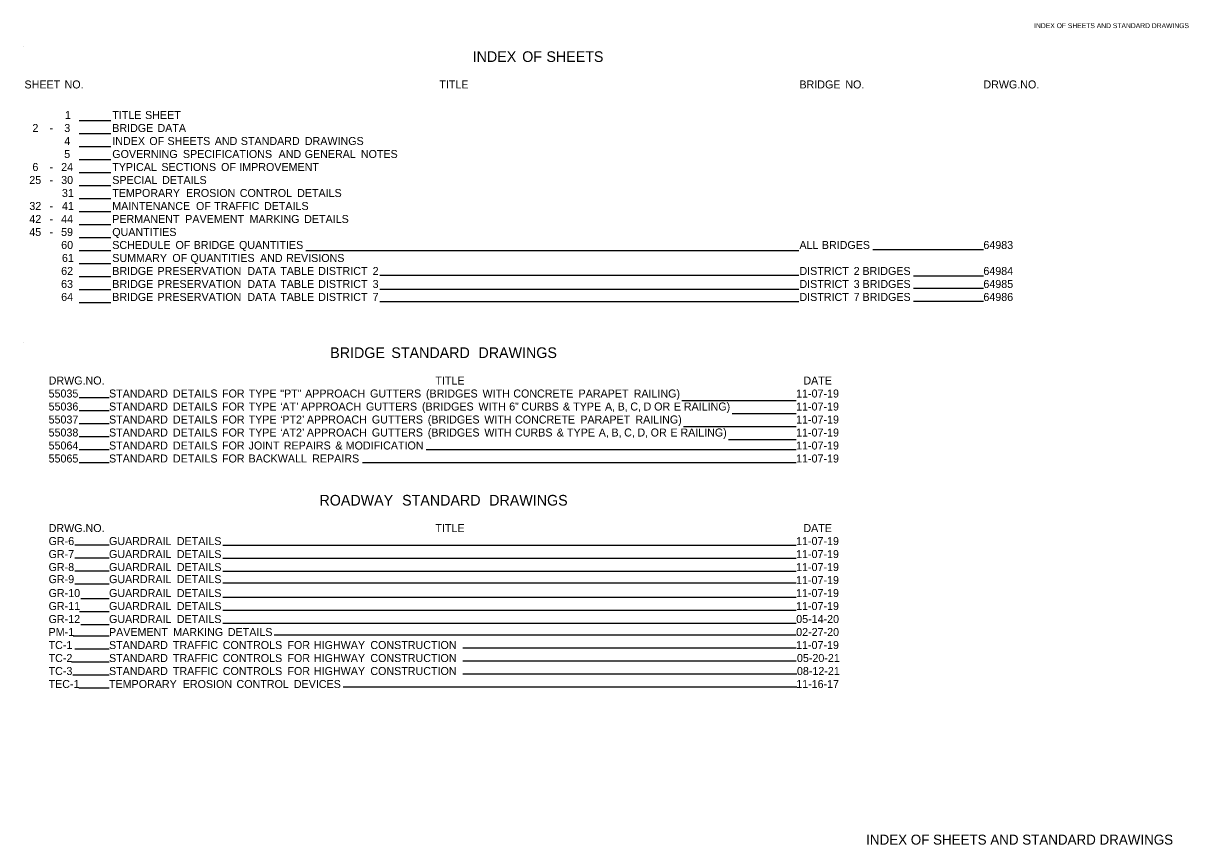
# Model space of a CAD drawing. Extents: x 1930556 to 1931949, y 596452 to 599546.
import ezdxf

# ---------------------------------------------------------------- set-up
doc = ezdxf.new("R2010")
doc.units = 0
for name, color, linetype in [('Default', 7, 'Continuous'), ('R_Border', 7, 'Continuous'), ('R_Border Prem', 7, 'Continuous')]:
    doc.layers.add(name, color=color, linetype=linetype)

msp = doc.modelspace()

# ---------------------------------------------------------------- linework, layer by layer
at = {"layer": 'Default'}
for p, q in [((1930556.1, 599518), (1930556.1, 599518)), ((1930623.2, 599429.1), (1930661.4, 599429.1)), ((1930623.2, 599413.5), (1930661.4, 599413.5)), ((1930623.2, 599397.9), (1930661.4, 599397.9)), ((1930623.2, 599382.3), (1930661.4, 599382.3)), ((1930623.2, 599366.7), (1930661.4, 599366.7)), ((1930623.2, 599351.1), (1930661.4, 599351.1)), ((1930623.2, 599335.5), (1930661.4, 599335.5)), ((1930623.2, 599319.9), (1930661.4, 599319.9)), ((1930623.2, 599304.3), (1930661.4, 599304.3)), ((1930623.2, 599288.7), (1930661.4, 599288.7)), ((1930623.2, 599273.1), (1930661.4, 599273.1)), ((1930895.4, 599273.3), (1931486.8, 599273.3)), ((1931575.7, 599274.2), (1931708.2, 599274.2)), ((1930623.2, 599257.5), (1930661.4, 599257.5)), ((1930623.2, 599241.9), (1930661.4, 599241.9)), ((1930983.9, 599243.4), (1931486.8, 599243.4)), ((1931624.2, 599242.6), (1931708.2, 599242.6)), ((1930623.2, 599226.3), (1930661.4, 599226.3)), ((1930983.9, 599226.7), (1931486.8, 599226.7)), ((1931624.2, 599227.8), (1931708.2, 599227.8)), ((1930623.2, 599210.7), (1930661.4, 599210.7)), ((1930983.9, 599211.9), (1931486.8, 599211.9)), ((1931624.2, 599212.4), (1931708.2, 599212.4)), ((1930556.1, 599162.6), (1930556.1, 599162.6)), ((1930623.3, 599096.7), (1930659.1, 599096.7)), ((1931346.3, 599093), (1931483.5, 599093)), ((1930623.2, 599081.1), (1930659.1, 599081.1)), ((1931406.6, 599077.4), (1931483.5, 599077.4)), ((1930623.2, 599065.5), (1930659.1, 599065.5)), ((1931348.5, 599061.8), (1931483.5, 599061.8)), ((1930623.3, 599049.9), (1930659.1, 599049.9)), ((1931402.4, 599046.2), (1931483.5, 599046.2)), ((1930623.3, 599034.3), (1930659.1, 599034.3)), ((1931039.7, 599034.2), (1931483.5, 599034.2)), ((1930623.3, 599018.7), (1930659.1, 599018.7)), ((1930963.4, 599018.6), (1931483.5, 599018.6)), ((1930618.1, 598919.8), (1930659.1, 598919.8)), ((1930795.8, 598919.5), (1931483.5, 598919.5)), ((1930618, 598904.2), (1930659.1, 598904.2)), ((1930795.8, 598903.9), (1931483.5, 598903.9)), ((1930618, 598888.6), (1930659.1, 598888.6)), ((1930795.8, 598888.3), (1931483.5, 598888.3)), ((1930618, 598873), (1930659.1, 598873)), ((1930795.8, 598874.2), (1931483.5, 598874.2)), ((1930625.4, 598855.3), (1930659.1, 598855.3)), ((1930795.8, 598857.1), (1931483.5, 598857.1)), ((1930623.6, 598839.7), (1930659.1, 598839.7)), ((1930795.8, 598841.5), (1931483.5, 598841.5)), ((1930625.4, 598824.1), (1930659.1, 598824.1)), ((1930795.8, 598825.9), (1931483.6, 598825.9)), ((1930616.1, 598810.5), (1930659.1, 598810.5)), ((1930857.1, 598811.8), (1931483.6, 598811.8)), ((1930617.9, 598794.9), (1930659.1, 598794.9)), ((1931083.6, 598796.2), (1931483.6, 598796.2)), ((1930613.9, 598779.3), (1930659.1, 598779.3)), ((1931083.6, 598780.6), (1931483.5, 598780.6)), ((1930615.7, 598763.7), (1930659.1, 598763.7)), ((1931083.6, 598765), (1931484.5, 598765)), ((1930622.8, 598748.2), (1930659.1, 598748.2)), ((1930940.1, 598749.4), (1931484.5, 598749.4))]:
    msp.add_line(p, q, dxfattribs=at)

# ---------------------------------------------------------------- texts
for s, height, p in [('INDEX', 12.8, (1931095.4, 599499.5)), (' OF', 12.8, (1931150.1, 599499.5)), (' SHEETS', 12.8, (1931179.1, 599499.5)), ('SHEET', 9.6, (1930557.7, 599467.7)), (' NO.', 9.6, (1930602.2, 599467.7)), ('TITLE', 9.6, (1931055.4, 599467.7)), ('BRIDGE', 9.6, (1931487.5, 599467.7)), (' NO.', 9.6, (1931539, 599467.7)), ('DRWG.NO.', 9.6, (1931708.2, 599467.7)), ('1', 9.6, (1930606.3, 599431)), ('TITLE', 9.6, (1930663, 599431)), (' SHEET', 9.6, (1930698.8, 599431)), ('2', 9.6, (1930567.2, 599415.4)), ('-', 9.6, (1930587.7, 599415.4)), ('3', 9.6, (1930605.4, 599415.4)), ('BRIDGE', 9.6, (1930663, 599415.4)), (' DATA', 9.6, (1930713.7, 599415.4)), ('4', 9.6, (1930605.4, 599399.8)), ('INDEX', 9.6, (1930663, 599399.8)), (' OF', 9.6, (1930703.9, 599399.8)), (' SHEETS', 9.6, (1930725.7, 599399.8)), (' AND', 9.6, (1930782.4, 599399.8)), (' STANDARD', 9.6, (1930813.7, 599399.8)), (' DRAWINGS', 9.6, (1930890.5, 599399.8)), ('5', 9.6, (1930605.3, 599384.2)), ('GOVERNING', 9.6, (1930663, 599384.2)), (' SPECIFICATIONS', 9.6, (1930744.2, 599384.2)), (' AND', 9.6, (1930859, 599384.2)), (' GENERAL', 9.6, (1930890.3, 599384.2)), (' NOTES', 9.6, (1930957.7, 599384.2)), ('6', 9.6, (1930567.2, 599368.6)), ('24', 9.6, (1930601.7, 599368.6)), ('TYPICAL', 9.6, (1930663, 599368.6)), (' SECTIONS', 9.6, (1930718.4, 599368.6)), (' OF', 9.6, (1930790, 599368.6)), (' IMPROVEMENT', 9.6, (1930811.8, 599368.6)), ('25', 9.6, (1930563.4, 599353)), ('-', 9.6, (1930587.7, 599368.6)), ('30', 9.6, (1930601.7, 599353)), ('SPECIAL', 9.6, (1930663, 599353)), (' DETAILS', 9.6, (1930719.2, 599353)), ('-', 9.6, (1930587.7, 599353)), ('31', 9.6, (1930602.6, 599337.4)), ('TEMPORARY', 9.6, (1930663, 599337.4)), (' EROSION', 9.6, (1930747.9, 599337.4)), (' CONTROL', 9.6, (1930812.4, 599337.4)), (' DETAILS', 9.6, (1930881.2, 599337.4)), ('32', 9.6, (1930563.5, 599321.8)), ('-', 9.6, (1930587.7, 599321.8)), ('41', 9.6, (1930602.6, 599321.8)), ('MAINTENANCE', 9.6, (1930663, 599321.8)), (' OF', 9.6, (1930759.9, 599321.8)), (' TRAFFIC', 9.6, (1930781.7, 599321.8)), (' DETAILS', 9.6, (1930841.5, 599321.8)), ('42', 9.6, (1930563.5, 599306.2)), ('-', 9.6, (1930587.7, 599306.2)), ('44', 9.6, (1930601.7, 599306.2)), ('PERMANENT', 9.6, (1930663, 599306.2)), (' PAVEMENT', 9.6, (1930747, 599306.2)), (' MARKING', 9.6, (1930824.2, 599306.2)), (' DETAILS', 9.6, (1930889.7, 599306.2)), ('45', 9.6, (1930563.4, 599290.6)), ('-', 9.6, (1930587.7, 599290.6)), ('59', 9.6, (1930601.6, 599290.6)), ('QUANTITIES', 9.6, (1930663, 599290.6)), ('60', 9.6, (1930601.7, 599275)), ('SCHEDULE', 9.6, (1930663, 599275)), (' OF', 9.6, (1930735.3, 599275)), (' BRIDGE', 9.6, (1930757.1, 599275)), (' QUANTITIES', 9.6, (1930811.5, 599275)), ('ALL', 9.6, (1931487.5, 599275)), (' BRIDGES', 9.6, (1931510.8, 599275)), ('64983', 9.6, (1931708.2, 599275)), ('61', 9.6, (1930602.6, 599259.4)), ('SUMMARY', 9.6, (1930663, 599259.4)), (' OF', 9.6, (1930731.5, 599259.4)), (' QUANTITIES', 9.6, (1930753.2, 599259.4)), (' AND', 9.6, (1930836.7, 599259.4)), (' REVISIONS', 9.6, (1930868.1, 599259.4)), ('62', 9.6, (1930601.7, 599243.8)), ('BRIDGE', 9.6, (1930663, 599243.8)), (' PRESERVATION', 9.6, (1930713.7, 599243.8)), (' DATA', 9.6, (1930821.5, 599243.8)), (' TABLE', 9.6, (1930861, 599243.8)), (' DISTRICT', 9.6, (1930906.5, 599243.8)), (' 2', 9.6, (1930971.8, 599243.8)), ('DISTRICT', 9.6, (1931487.5, 599243.8)), (' 2', 9.6, (1931549, 599243.8)), (' BRIDGES', 9.6, (1931559.5, 599243.8)), ('64984', 9.6, (1931708.2, 599243.8)), ('63', 9.6, (1930601.6, 599228.2)), ('BRIDGE', 9.6, (1930663, 599228.2)), (' PRESERVATION', 9.6, (1930713.7, 599228.2)), (' DATA', 9.6, (1930821.5, 599228.2)), (' TABLE', 9.6, (1930861, 599228.2)), (' DISTRICT', 9.6, (1930906.5, 599228.2)), (' 3', 9.6, (1930971.8, 599228.2)), ('DISTRICT', 9.6, (1931487.5, 599228.2)), (' 3', 9.6, (1931549, 599228.2)), (' BRIDGES', 9.6, (1931559.6, 599228.2)), ('64985', 9.6, (1931708.2, 599228.2)), ('64', 9.6, (1930601.7, 599212.6)), ('BRIDGE', 9.6, (1930663, 599212.6)), (' PRESERVATION', 9.6, (1930713.7, 599212.6)), (' DATA', 9.6, (1930821.5, 599212.6)), (' TABLE', 9.6, (1930861, 599212.6)), (' DISTRICT', 9.6, (1930906.5, 599212.6)), (' 7', 9.6, (1930971.8, 599212.6)), ('DISTRICT', 9.6, (1931487.5, 599212.6)), (' 7', 9.6, (1931549, 599212.6)), (' BRIDGES', 9.6, (1931559.6, 599212.6)), ('64986', 9.6, (1931708.2, 599212.6)), ('BRIDGE', 12.8, (1930924.5, 599144.1)), (' STANDARD', 12.8, (1930993.1, 599144.1)), (' DRAWINGS', 12.8, (1931097.6, 599144.1)), ('DRWG.NO.', 9.6, (1930586.7, 599112.3)), ('TITLE', 9.6, (1931050.7, 599112.3)), ('DATE', 9.6, (1931492.2, 599112.3)), ('55035', 9.6, (1930586.6, 599096.7)), ('STANDARD', 9.6, (1930659.1, 599096.7)), (' DETAILS', 9.6, (1930732.2, 599096.7)), (' FOR', 9.6, (1930791.1, 599096.7)), (' TYPE', 9.6, (1930823, 599096.7)), (' "PT"', 9.6, (1930861, 599096.7)), (' APPROACH', 9.6, (1930890.8, 599096.7)), (' GUTTERS', 9.6, (1930968.7, 599096.7)), (' (BRIDGES', 9.6, (1931035.8, 599096.7)), (' WITH', 9.6, (1931103.7, 599096.7)), (' CONCRETE', 9.6, (1931140.6, 599096.7)), (' PARAPET', 9.6, (1931218.9, 599096.7)), (' RAILING)', 9.6, (1931285, 599096.7)), ('11-07-19', 9.6, (1931483.5, 599096.7)), ('55036', 9.6, (1930586.6, 599081.1)), ('STANDARD', 9.6, (1930659.1, 599081.1)), (' DETAILS', 9.6, (1930732.2, 599081.1)), (' FOR', 9.6, (1930791.1, 599081.1)), (' TYPE', 9.6, (1930823, 599081.1)), ('‘', 9.6, (1930864.7, 599081.1)), ('AT', 9.6, (1930867, 599081.1)), ('’', 9.6, (1930883.8, 599081.1)), (' APPROACH', 9.6, (1930885.9, 599081.1)), (' GUTTERS', 9.6, (1930963.8, 599081.1)), (' (BRIDGES', 9.6, (1931031, 599081.1)), (' WITH', 9.6, (1931098.8, 599081.1)), (' 6', 9.6, (1931135.7, 599081.1)), ('”', 9.6, (1931146.3, 599081.1)), (' CURBS', 9.6, (1931150.2, 599081.1)), (' &', 9.6, (1931200.2, 599081.1)), (' TYPE', 9.6, (1931212.5, 599081.1)), (' A,', 9.6, (1931250.6, 599081.1)), (' B,', 9.6, (1931265.8, 599081.1)), (' C,', 9.6, (1931281, 599081.1)), (' D', 9.6, (1931296.9, 599081.1)), (' OR', 9.6, (1931309.6, 599081.1)), (' E', 9.6, (1931333.3, 599081.1)), (' RAILING)', 9.6, (1931345.2, 599081.1)), ('11-07-19', 9.6, (1931483.5, 599081.1)), ('55037', 9.6, (1930586.6, 599065.5)), ('STANDARD', 9.6, (1930659.1, 599065.5)), (' DETAILS', 9.6, (1930732.2, 599065.5)), (' FOR', 9.6, (1930791.1, 599065.5)), (' TYPE', 9.6, (1930823, 599065.5)), ('‘', 9.6, (1930864.7, 599065.5)), ('PT2', 9.6, (1930867, 599065.5)), ('’', 9.6, (1930890.8, 599065.5)), (' APPROACH', 9.6, (1930892.9, 599065.5)), (' GUTTERS', 9.6, (1930970.9, 599065.5)), (' (BRIDGES', 9.6, (1931038, 599065.5)), (' WITH', 9.6, (1931105.8, 599065.5)), (' CONCRETE', 9.6, (1931142.7, 599065.5)), (' PARAPET', 9.6, (1931221, 599065.5)), (' RAILING)', 9.6, (1931287.1, 599065.5)), ('11-07-19', 9.6, (1931483.5, 599065.5)), ('55038', 9.6, (1930586.6, 599049.9)), ('STANDARD', 9.6, (1930659.1, 599049.9)), (' DETAILS', 9.6, (1930732.2, 599049.9)), (' FOR', 9.6, (1930791.1, 599049.9)), (' TYPE', 9.6, (1930823, 599049.9)), ('‘', 9.6, (1930864.7, 599049.9)), ('AT2', 9.6, (1930867, 599049.9)), ('’', 9.6, (1930890.8, 599049.9)), (' APPROACH', 9.6, (1930892.9, 599049.9)), (' GUTTERS', 9.6, (1930970.9, 599049.9)), (' (BRIDGES', 9.6, (1931038, 599049.9)), (' WITH', 9.6, (1931105.8, 599049.9)), (' CURBS', 9.6, (1931142.7, 599049.9)), (' &', 9.6, (1931192.7, 599049.9)), (' TYPE', 9.6, (1931205.1, 599049.9)), (' A,', 9.6, (1931243.1, 599049.9)), (' B,', 9.6, (1931258.4, 599049.9)), (' C,', 9.6, (1931273.6, 599049.9)), (' D,', 9.6, (1931289.5, 599049.9)), (' OR', 9.6, (1931305.4, 599049.9)), (' E', 9.6, (1931329.1, 599049.9)), (' RAILING)', 9.6, (1931341.1, 599049.9)), ('11-07-19', 9.6, (1931483.5, 599049.9)), ('55064', 9.6, (1930586.6, 599034.3)), ('STANDARD', 9.6, (1930659.1, 599034.3)), (' DETAILS', 9.6, (1930732.2, 599034.3)), (' FOR', 9.6, (1930791.1, 599034.3)), (' JOINT', 9.6, (1930823, 599034.3)), (' REPAIRS', 9.6, (1930865.2, 599034.3)), (' &', 9.6, (1930927.1, 599034.3)), (' MODIFICATION', 9.6, (1930939.5, 599034.3)), ('11-07-19', 9.6, (1931483.5, 599034.3)), ('55065', 9.6, (1930586.6, 599018.7)), ('STANDARD', 9.6, (1930659.1, 599018.7)), (' DETAILS', 9.6, (1930732.2, 599018.7)), (' FOR', 9.6, (1930791.1, 599018.7)), (' BACKWALL', 9.6, (1930823, 599018.7)), (' REPAIRS', 9.6, (1930899.3, 599018.7)), ('11-07-19', 9.6, (1931483.5, 599018.7)), ('ROADWAY', 12.8, (1930911.6, 598967)), (' STANDARD', 12.8, (1931006, 598967)), (' DRAWINGS', 12.8, (1931110.5, 598967)), ('DRWG.NO.', 9.6, (1930586.7, 598935.2)), ('TITLE', 9.6, (1931050.7, 598935.2)), ('DATE', 9.6, (1931492.2, 598935.2)), ('GR-6', 9.6, (1930586.6, 598919.6)), ('GUARDRAIL', 9.6, (1930659.1, 598919.6)), (' DETAILS', 9.6, (1930736.9, 598919.6)), ('11-07-19', 9.6, (1931483.5, 598919.6)), ('GR-7', 9.6, (1930586.6, 598904)), ('GUARDRAIL', 9.6, (1930659.1, 598904)), (' DETAILS', 9.6, (1930736.9, 598904)), ('11-07-19', 9.6, (1931483.5, 598904)), ('GR-8', 9.6, (1930586.6, 598888.4)), ('GUARDRAIL', 9.6, (1930659.1, 598888.4)), (' DETAILS', 9.6, (1930736.9, 598888.4)), ('11-07-19', 9.6, (1931483.5, 598888.4)), ('GR-9', 9.6, (1930586.6, 598873.9)), ('GUARDRAIL', 9.6, (1930659.1, 598873.9)), (' DETAILS', 9.6, (1930736.9, 598873.9)), ('11-07-19', 9.6, (1931483.5, 598872.8)), ('GR-10', 9.6, (1930586.6, 598857.2)), ('GUARDRAIL', 9.6, (1930659.1, 598857.2)), (' DETAILS', 9.6, (1930736.9, 598857.2)), ('11-07-19', 9.6, (1931483.5, 598857.2)), ('GR-11', 9.6, (1930586.6, 598841.6)), ('GUARDRAIL', 9.6, (1930659.1, 598841.6)), (' DETAILS', 9.6, (1930736.9, 598841.6)), ('11-07-19', 9.6, (1931483.5, 598841.6)), ('GR-12', 9.6, (1930586.6, 598826)), ('GUARDRAIL', 9.6, (1930659.1, 598826)), (' DETAILS', 9.6, (1930736.9, 598826)), ('05-14-20', 9.6, (1931483.6, 598826)), ('PM-1', 9.6, (1930586.6, 598810.4)), ('PAVEMENT', 9.6, (1930659.1, 598810.4)), (' MARKING', 9.6, (1930732.6, 598810.4)), (' DETAILS', 9.6, (1930798.1, 598810.4)), ('02-27-20', 9.6, (1931483.6, 598810.4)), ('TC-1', 9.6, (1930586.6, 598794.8)), ('STANDARD', 9.6, (1930659.1, 598794.8)), (' TRAFFIC', 9.6, (1930732.2, 598794.8)), (' CONTROLS', 9.6, (1930792, 598794.8)), (' FOR', 9.6, (1930869.6, 598794.8)), (' HIGHWAY', 9.6, (1930901.4, 598794.8)), (' CONSTRUCTION', 9.6, (1930969.1, 598794.8)), ('11-07-19', 9.6, (1931483.5, 598794.8)), ('TC-2', 9.6, (1930586.6, 598779.2)), ('STANDARD', 9.6, (1930659.1, 598779.2)), (' TRAFFIC', 9.6, (1930732.2, 598779.2)), (' CONTROLS', 9.6, (1930792, 598779.2)), (' FOR', 9.6, (1930869.6, 598779.2)), (' HIGHWAY', 9.6, (1930901.4, 598779.2)), (' CONSTRUCTION', 9.6, (1930969.1, 598779.2)), ('05-20-21', 9.6, (1931484.5, 598779.2)), ('TC-3', 9.6, (1930586.6, 598763.6)), ('STANDARD', 9.6, (1930659.1, 598763.6)), (' TRAFFIC', 9.6, (1930732.2, 598763.6)), (' CONTROLS', 9.6, (1930792, 598763.6)), (' FOR', 9.6, (1930869.6, 598763.6)), (' HIGHWAY', 9.6, (1930901.4, 598763.6)), (' CONSTRUCTION', 9.6, (1930969.1, 598763.6)), ('08-12-21', 9.6, (1931484.5, 598763.6)), ('TEC-1', 9.6, (1930586.6, 598748)), ('TEMPORARY', 9.6, (1930659.1, 598748)), (' EROSION', 9.6, (1930744, 598748)), (' CONTROL', 9.6, (1930808.5, 598748)), (' DEVICES', 9.6, (1930877.3, 598748)), ('11-16-17', 9.6, (1931483.6, 598748))]:
    msp.add_text(s, height=height, rotation=360, dxfattribs=at).set_placement(p)
at = {"layer": 'R_Border'}
msp.add_text('INDEX OF SHEETS AND STANDARD DRAWINGS', height=12, rotation=360, dxfattribs=at).set_placement((1931567.6, 598560))
at = {"layer": 'R_Border Prem'}
msp.add_text('INDEX OF SHEETS AND STANDARD DRAWINGS', height=5.862, rotation=360, dxfattribs=at).set_placement((1931769.1, 599540.1))

doc.saveas('drawing.dxf')
